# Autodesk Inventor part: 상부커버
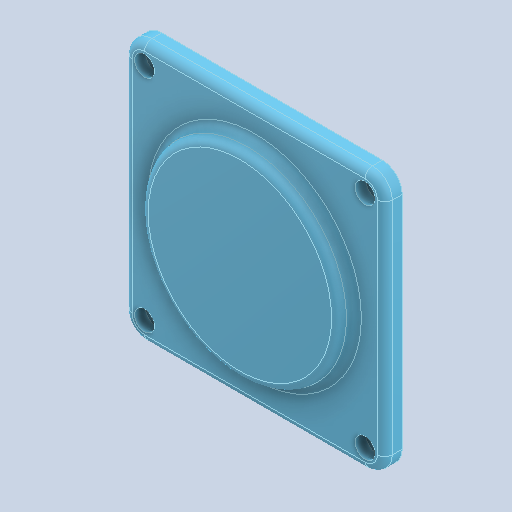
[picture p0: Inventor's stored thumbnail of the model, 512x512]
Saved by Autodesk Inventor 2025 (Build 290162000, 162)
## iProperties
Created: 2024-08
Part Number: 상부커버
Material: 알루미늄 6061
Document SubType Name: Modeling
Designer: rese9
Density: 2.71 g/cm^3
Appearance: 기본값
Author: jhkim
Sending System: Autodesk Inventor 2025
Preprocessor: ST-DEVELOPER v20
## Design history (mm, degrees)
feature "솔리드2"
node "솔리드1"
